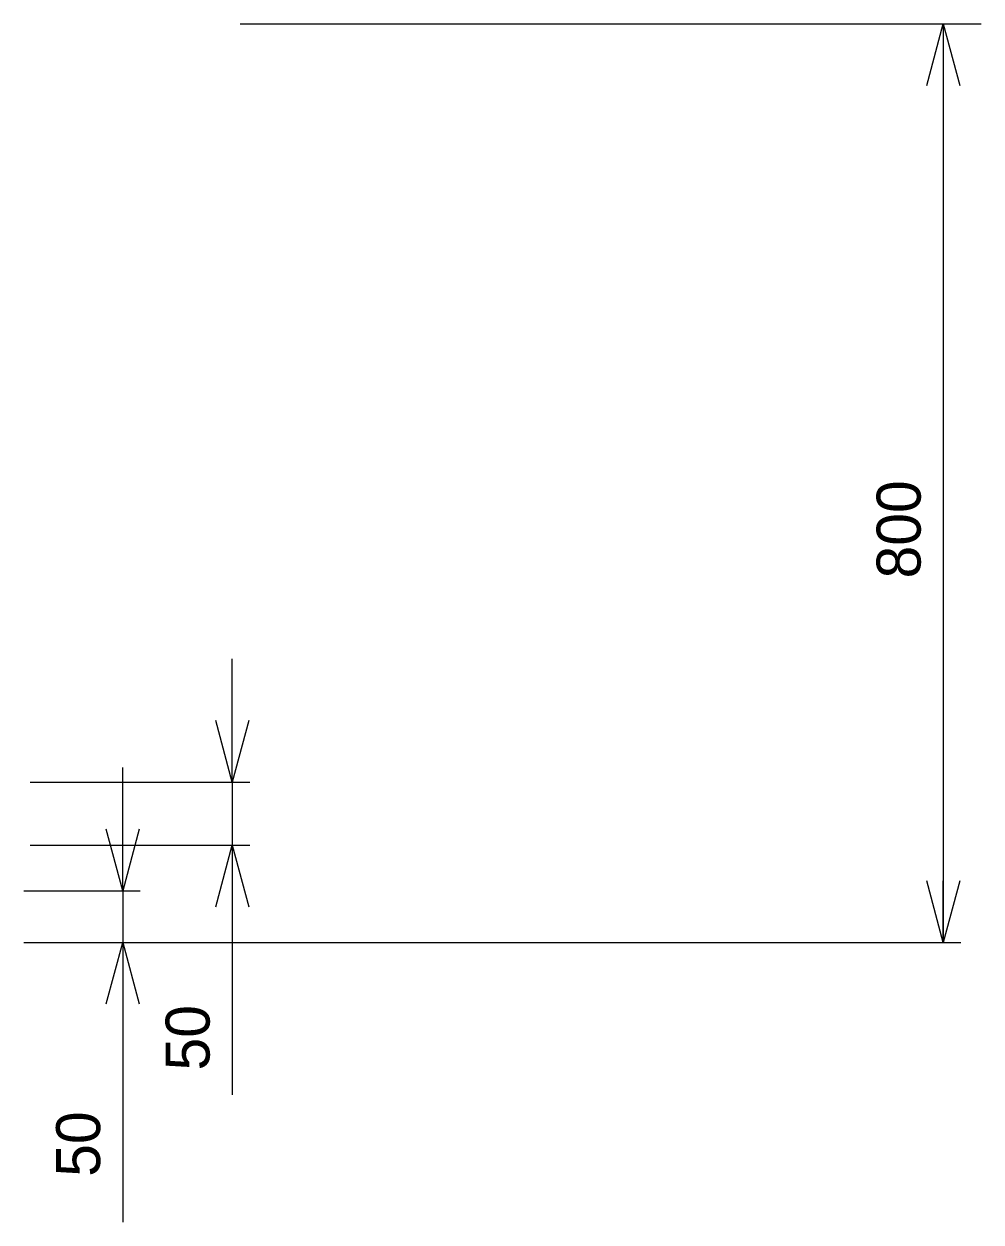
# Model space of a CAD drawing. Extents: x -880561 to -880093, y -1023300 to -1022369.
# Drawn here: x -880497.8 to -880454.3, y -1022916.2 to -1022861.8 of the extents above; entities that cross this region are included whole.
import ezdxf

# ---------------------------------------------------------------- set-up
doc = ezdxf.new("R2010")
doc.units = 0
doc.layers.add('podzemní stavby', color=7, linetype='Continuous')
doc.layers.add('vedeni NN VN', color=7, linetype='Continuous')

# ---------------------------------------------------------------- blocks, each defined once
blk = doc.blocks.new('PEN30')
at = {"layer": 'vedeni NN VN'}
for p, q in [((-1, 0.268), (0, 0)), ((0, 0), (-1, -0.268)), ((0, 0), (-1, 0))]:
    blk.add_line(p, q, dxfattribs=at)

msp = doc.modelspace()

# ---------------------------------------------------------------- linework, layer by layer
at = {"layer": 'podzemní stavby'}
for p, q in [((-880487.957, -1022861.76), (-880454.282, -1022861.76)), ((-880455.997, -1022864.56), (-880455.997, -1022903.51)), ((-880488.314, -1022893.42), (-880488.314, -1022890.62)), ((-880493.292, -1022898.36), (-880493.292, -1022895.56)), ((-880497.492, -1022896.22), (-880487.514, -1022896.22)), ((-880488.314, -1022896.22), (-880488.314, -1022899.089)), ((-880497.492, -1022899.089), (-880487.514, -1022899.089)), ((-880497.781, -1022901.16), (-880492.492, -1022901.16)), ((-880493.292, -1022901.16), (-880493.292, -1022903.51)), ((-880488.314, -1022901.889), (-880488.314, -1022910.439)), ((-880497.781, -1022903.51), (-880492.492, -1022903.51)), ((-880497.581, -1022903.51), (-880455.197, -1022903.51)), ((-880493.292, -1022906.31), (-880493.292, -1022916.224))]:
    msp.add_line(p, q, dxfattribs=at)

# ---------------------------------------------------------------- block references
for p, xscale, yscale, rotation in [((-880455.997, -1022861.76), 2.8000000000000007, 2.8000000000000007, 90.00000000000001), ((-880455.997, -1022861.76), 2.8000000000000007, 2.8000000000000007, 90.00000000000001), ((-880455.997, -1022861.76), 2.8000000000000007, 2.8000000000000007, 90.00000000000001), ((-880488.314, -1022896.22), 2.8000000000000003, 2.8000000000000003, -90.00000000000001), ((-880493.292, -1022901.16), 2.8000000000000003, 2.8000000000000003, -90.00000000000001), ((-880488.314, -1022899.089), 2.8000000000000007, 2.8000000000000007, 90.00000000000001), ((-880455.997, -1022903.51), 2.8000000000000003, 2.8000000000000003, -90.00000000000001), ((-880455.997, -1022903.51), 2.8000000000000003, 2.8000000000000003, -90.00000000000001), ((-880455.997, -1022903.51), 2.8000000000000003, 2.8000000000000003, -90.00000000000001), ((-880493.292, -1022903.51), 2.8000000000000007, 2.8000000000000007, 90.00000000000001)]:
    msp.add_blockref('PEN30', p, dxfattribs=dict(at, xscale=xscale, yscale=yscale, rotation=rotation))

# ---------------------------------------------------------------- texts
for s, p in [('800', (-880457.027, -1022886.967)), ('50', (-880489.343, -1022909.335)), ('50', (-880494.319, -1022914.167))]:
    msp.add_text(s, height=2, rotation=90, dxfattribs=at).set_placement(p)

doc.saveas('drawing.dxf')
